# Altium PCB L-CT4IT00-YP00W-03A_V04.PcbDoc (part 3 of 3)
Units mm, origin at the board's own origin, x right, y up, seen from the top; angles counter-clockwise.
Board outline 52 x 31.8 mm, 4 copper layers (Top Layer, Layer 1, Layer 2, Bottom Layer), stack 1.288 mm thick; 160 components, 112 nets, 631 pads, 1087 vias.
Unrouted connection lines stored in the file: 130.
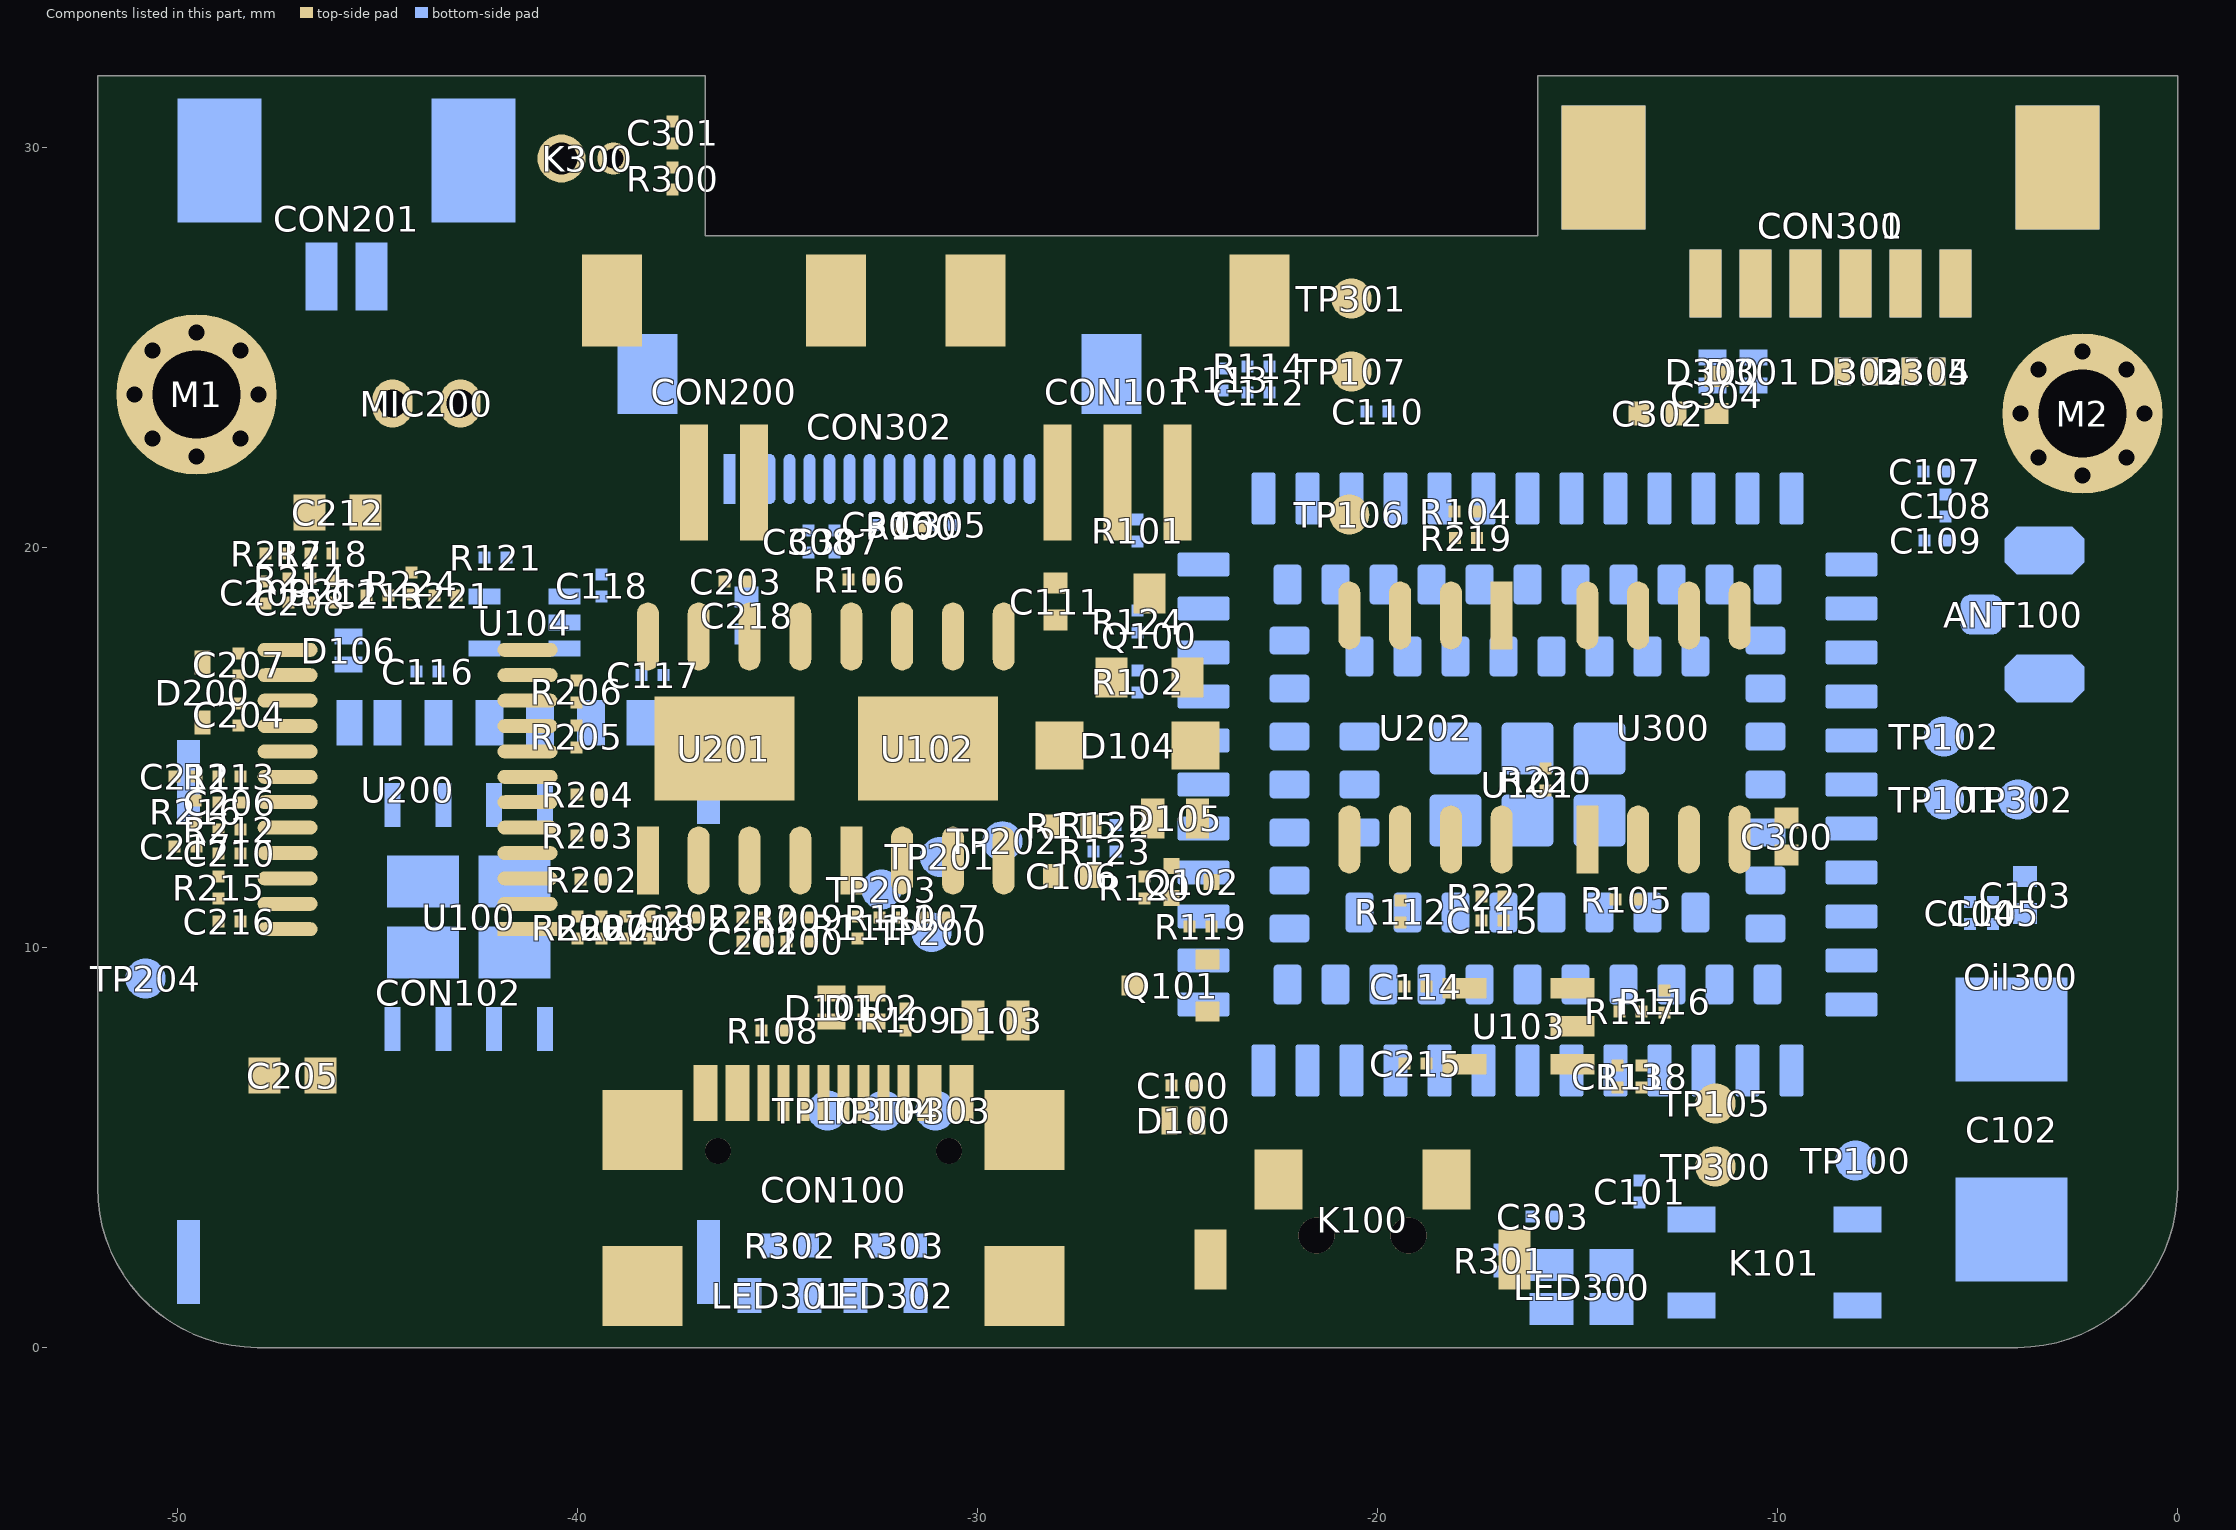
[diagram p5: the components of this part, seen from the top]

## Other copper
Top Layer:
  pour cut-out: -17.424,17.196 -17.455,17.227 -17.959,17.227 -17.959,17.634 -18,17.675 -17.95,17.725 -17.375,17.725 -17.375,17.245
  region net VBAT: -35.975,17.1 -35.825,16.95 -35.184,16.95 -35.025,17.109 -35.025,19.275 -35.6,19.85 -35.975,19.85
  region net VBAT: -15.85,6.625 -15.7,6.775 -15.7,7.35 -15.65,7.4 -14.6,7.4 -14.525,7.325 -14.525,6.775 -14.4,6.65 -5.412,6.65 -5.212,6.45 -5.212,5.713 -5.375,5.55 -20.678,5.55 -23.6,8.472 -23.6,9.15 -23.775,9.325 -24.453,9.325 -24.55,9.422 -24.55,10 -24.3,10.25 -24.3,10.65 -24.275,10.675 -23.75,10.675 -23.675,10.75 -23.675,11.9 -24.301,12.526 -24.75,12.526 -24.825,12.601 -24.825,13.75 -25.15,14.075 -25.15,17.25 -24.325,17.25 -23.875,16.8 -23.875,13.725 -22.45,12.3 -22.45,9.075 -20,6.625
  region net VBAT_Li: -29.625,17.05 -29.625,18.475 -29.475,18.625 -27.55,18.625 -26.351,19.825 -25.875,19.825 -25.392,20.308 -25.392,23.223 -24.477,23.223 -24.475,19.15 -25.275,18.35 -26.4,18.35 -27.825,16.925 -29.5,16.925
  pour cut-out: -14.984,13.793 -14.984,11.611 -11.1,11.611 -11.1,13.739
  pour cut-out: -21.05,11.625 -16.356,11.625 -16.356,13.781 -21.05,13.781
  region net VBUS: -28.2,10.925 -28.2,10.127 -29.797,8.529 -29.8,8.529 -29.8,7.734 -30.259,7.275 -31.4,7.275 -31.4,7.875 -31.075,7.875 -30.75,8.2 -30.75,10.016 -30.716,10.05 -30.283,10.05 -29.65,10.664 -29.65,12.9 -29.5,13.05 -29.2,13.05 -28.9,13.35 -28.9,14.7 -28.55,15.05 -28.55,15.65 -28.375,15.65 -27.05,16.975 -27.05,17.25 -26.225,17.25 -26.225,16.139 -27.35,15.014 -27.35,14.45 -27.825,13.975 -27.825,11.3
  pour cut-out: -25.896,23.329 -25.604,23.329 -25.604,19.921 -25.896,19.921
  pour cut-out: -36.481,23.329 -36.189,23.329 -36.189,19.921 -36.481,19.921
  pour cut-out: -35.171,18.879 -28.81,18.879 -28.81,16.7 -35.158,16.7
  pour cut-out: -40.78,13.279 -31.35,13.279 -31.35,11.342 -40.769,11.342
Layer 1:
  pour cut-out: -32.95,19.025 -33.6,18.375 -33.6,18.151 -33.249,17.8 -32.9,17.8 -32.9,18.975
Layer 2:
  rectangle net GND: -49.175,10.9 -47.625,18.825
  pour cut-out: -17.308,9.955 -17.308,9.997 -16.906,10.399 -16.748,10.242 -16.765,10.242 -17.18,9.827 -17.3,9.947 -17.3,9.955
  pour cut-out: -30.2,22.75 -30.17,22.78 -29.601,22.78 -29.601,22.557 -29.613,22.569 -30.2,22.569 -30.2,22.739 -30.194,22.745
  pour cut-out: -4.825,19.825 -4.825,16.825 -1.825,16.825 -1.825,19.825
Bottom Layer:
  pour cut-out: -11.289,20.622 -11.289,19.663 -11.713,19.663 -11.832,19.782 -11.832,20.622 -11.303,20.622 -11.29,20.635
  region net VBAT: -6.5,7.075 -5.8,7.075 -5.55,7.325 -5.55,9.35 -5.95,9.75 -6.5,9.75 -7.25,10.5 -7.25,12.1 -7.175,12.175 -6.525,12.175 -6.375,12.025 -6.375,11 -6.125,10.75 -4.313,10.75 -4.163,10.9 -4.163,11.087 -4.125,11.125 -2.85,11.125 -2.7,10.975 -2.7,5.875 -2.9,5.675 -6.375,5.675 -6.5,5.8
  region net VBAT: -34.821,19.637 -34.821,18.704 -35.05,18.475 -36.05,18.475 -36.275,18.7 -36.275,19.65 -36.037,19.888 -35.072,19.888
  pour cut-out: -41.625,8.769 -41.625,8.975 -41.775,8.975 -41.8,8.95 -41.8,8.75 -41.644,8.75
  pour cut-out: -4.825,19.825 -4.825,16.825 -1.825,16.825 -1.825,19.825
  pour cut-out: -35.146,0.611 -32.104,0.611 -32.104,1.989 -35.146,1.989

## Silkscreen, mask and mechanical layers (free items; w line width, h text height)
Top Overlay:
  circle w0.2: c-2.375,23.35 r2.2
  circle w0.2: c-49.525,23.825 r2.2
  text "GND" at -19.775,25.85 h1.3
  text "VDD_EXT" at -19.825,24.15 h1.3
  text "BOOT" at -20.122,21.178 h1.3
  text "SPK_N" at -31.425,21.075 h1.3 r90
  text "SPK_P" at -40.7,18.325 h1.3 r90
  text "VBAT" at -14.8,5.425 h1.3
  text "S/C" at -4.975,4.4 h1.5
  text "GND" at -14.8,4.125 h1.3
  text "L-CT4IT00-YP00W-03A_V04" at -6.85,2.725 h1.5 r90
  text "YYWW" at -5.825,2.725 h1.5
Bottom Overlay:
  text "MIC_P" at -47.85,26.375 h1.3
  text "MIC_N" at -40.25,26.375 h1.3
  text "GND" at -31.1,22.203 h1.3
  text "U0_RX" at -6.796,16.289 h1.3 r270
  text "GXTX" at -30.65,13.275 h1.3
  text "GXRX" at -27.875,13.275 h1.3
  text "GND" at -2.965,12.727 h1.3 r270
  text "U0_TX" at -6.796,9.996 h1.3 r270
  text "GXBOOT" at -32.4,9.925 h1.3
  text "GXRST" at -27.2,9.925 h1.3
  text "GND" at -31.415,6.852 h1.3 r270
  text "DN" at -34.175,6.825 h1.3 r270
  text "DP" at -32.775,6.84 h1.3 r270
  text "GXDBG" at -51,5.025 h1.3 r270
  text "PWRKEY" at -8.875,4.3 h1.3
Top Mechanical 1/Mechanical 2:
  drawing of 177 lines, arcs and shapes, not listed
Bottom Mechanical 1/Mechanical 2:
  circle w0.006: c0,31.8 r0.003
  circle w0.006: c-4,0 r0.003

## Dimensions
-52,0 to -52,31.8 on Top Mechanical 1/Mechanical 2
-52,0 to 0,0 on Top Mechanical 1/Mechanical 2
